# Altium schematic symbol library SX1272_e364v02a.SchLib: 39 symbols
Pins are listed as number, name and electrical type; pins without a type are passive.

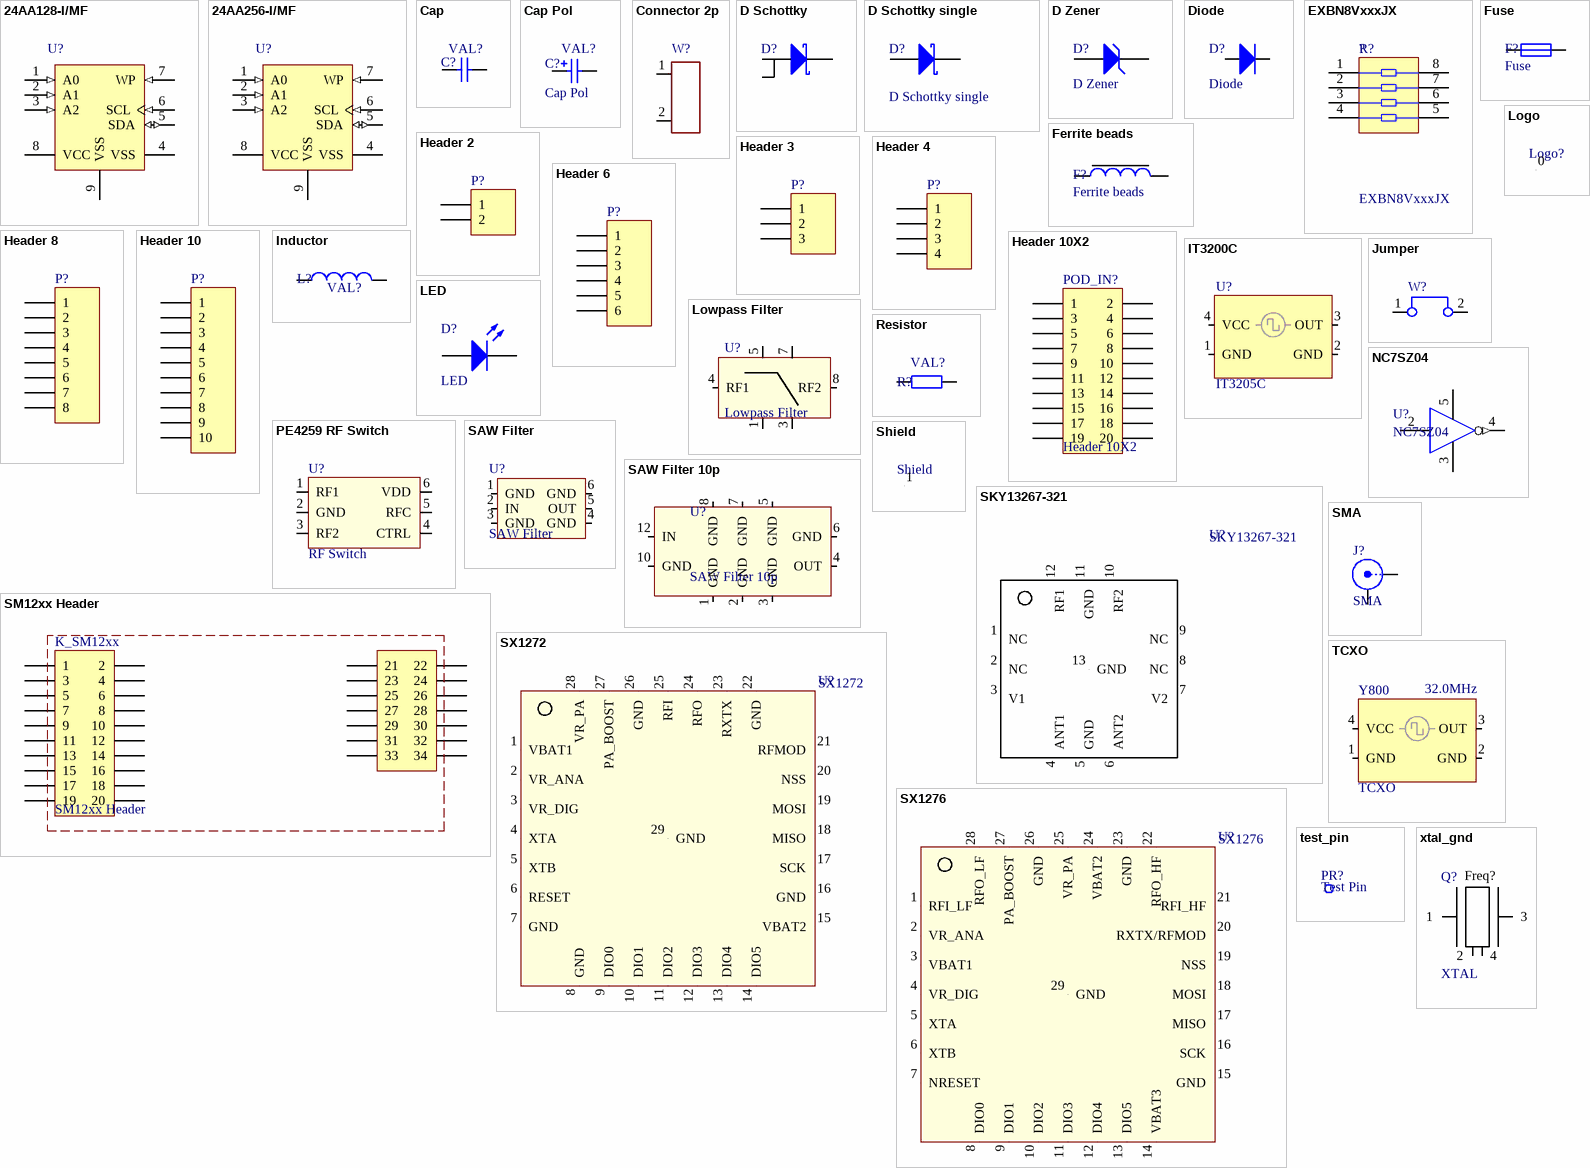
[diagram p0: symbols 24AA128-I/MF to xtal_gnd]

## 24AA128-I/MF
designator U?
128kbit, 400kHz, 1.7V, 8-Pin DFN, Industrial Temperature
footprint DFN8_ 5x6mm (8 Leads, Body 5x6mm, pitch 1.27mm, DFN8)
pins: 1 A0 (in), 2 A1 (in), 3 A2 (in), 4 VSS (power), 5 SDA (io), 6 SCL (in), 7 WP (in), 8 VCC (power), 9 VSS (power)

## 24AA256-I/MF
designator U?
256kbit, 400kHz, 1.7V, 8-Pin DFN, Industrial Temperature
footprint DFN8_ 5x6mm (8 Leads, Body 5x6mm, pitch 1.27mm, DFN8)
pins: 1 A0 (in), 2 A1 (in), 3 A2 (in), 4 VSS (power), 5 SDA (io), 6 SCL (in), 7 WP (in), 8 VCC (power), 9 VSS (power)

## Cap
designator C?  value VAL?  (hidden comment: Cap)
Capacitor SMD
simulation model CAP (Semiconductor Capacitor)
signal-integrity model Cap Semi
footprint rlc_402_smd (Chip SMD component 402; Body 1.0 x 0.5 mm (LxW typ))
footprint rlc_603_smd (Chip SMD component 603; Body 1.6 x 0.8mm (LxW typ))
footprint rlc_805_smd (Chip SMD component 805; Body 2.0 x 1.25 mm (LxW typ))
footprint rlc_1206_smd (Chip SMD component 1206; Body 3.2 x 1.6 mm (LxW typ))
footprint rlc_201_smd (Chip SMD component 201; Body 0.6 x 0.3 mm (LxW typ))
pins: 1, 2

## Cap Pol
designator C?  value VAL?
Polarized Capacitor (Surface Mount)
simulation model CAP (Capacitor)
signal-integrity model Cap Pol
footprint rlc_1210_smd (Chip SMD component 1210; Body 3.2 x 2.5 mm (LxW typ))
footprint rlc_1812_smd (Chip SMD component 1812; Body 4.5 x 3.2 mm (LxW typ))
footprint rlc_2225_smd (Chip SMD component 2225; Body 5.6 x 6.4 mm (LxW typ))
footprint CD3216-1206 (Chip Diode; Body 3.2 x 1.6 mm (LxW typ))
footprint CD2012-0805 (Chip Diode; Body 2.0 x 1.3 mm (LxW typ))
footprint rlc_1206_smd capa pol (Chip SMD component 1206; Body 3.2 x 1.6 mm (LxW typ))
pins: 1, 2
1 alternate drawing of the same symbol

## Connector 2p
designator W?  (value not drawn)
2pins Connector
footprint Connector 2p 2_54mm (Generic connector 2.54mm, 2 Leads 1mm;)
pins: 1, 2

## D Schottky
designator D?
Schottky Diode
footprint DPAK-369C-01 (DPAK-369C-01, 3-Leads, Body 6x6.22mm, Pitch 2.3mm, IPC Medium Density)
pins: 1 A, 3 A, 4 K

## D Schottky single
designator D?
Schottky Diode
footprint SOD123 (SOD123; Chip Diode; Body  2.7 x 1.6 mm (LxW typ))
pins: 1 A, 2 K

## D Zener
designator D?
Zener Diode
footprint CD1608-0603 (Chip Diode; Body 1.6 x 0.8 mm (LxW typ))
footprint CD2012-0805 (Chip Diode; Body 2.0 x 1.3 mm (LxW typ))
pins: 1 A, 2 K

## Diode
designator D?
Protection Diode
footprint CD1005-0402 (Chip Diode; Body 1.0 x 0.5 mm (LxW typ))
footprint CD1608-0603 (Chip Diode; Body 1.6 x 0.8 mm (LxW typ))
footprint CD2012-0805 (Chip Diode; Body 2.0 x 1.3 mm (LxW typ))
footprint CD3216-1206 (Chip Diode; Body 3.2 x 1.6 mm (LxW typ))
footprint PowerDI 123 (Chip Diode; PowerDI 123)
footprint DO214-AA (Chip Diode; Body 4.3 x3.6mm (LxW typ))
pins: 1 A, 2 K

## EXBN8VxxxJX
designator R?
Mini-Flat Package, Isolated Resistor Network, 0.031 W/resistor
footprint EXB28V (Chip Resistor Array, (0402x4); SM; 8 Leads; Body 2.10 x 1.10 mm (LxW max))
pins: 1, 2, 3, 4, 5, 6, 7, 8

## Ferrite beads
designator F?
Value: VAL?
footprint rlc_1206_smd (Chip SMD component 1206; Body 3.2 x 1.6 mm (LxW typ))
footprint rlc_805_smd (Chip SMD component 805; Body 2.0 x 1.25 mm (LxW typ))
footprint rlc_603_smd (Chip SMD component 603; Body 1.6 x 0.8mm (LxW typ))
footprint rlc_402_smd (Chip SMD component 402; Body 1.0 x 0.5 mm (LxW typ))
pins: 1, 2

## Fuse
designator F?
simulation model FUSE (Spice Subcircuit)
footprint rlc_1206_smd (Chip SMD component 1206; Body 3.2 x 1.6 mm (LxW typ))
footprint rlc_805_smd (Chip SMD component 805; Body 2.0 x 1.25 mm (LxW typ))
footprint rlc_603_smd (Chip SMD component 603; Body 1.6 x 0.8mm (LxW typ))
footprint rlc_402_smd (Chip SMD component 402; Body 1.0 x 0.5 mm (LxW typ))
pins: 1, 2

## Header 2
designator P?
Header, 2-Pin
footprint HDR1X2 (Connector; Header; 2 Position)
signal-integrity model Connector
pins: 1, 2

## Header 3
designator P?
Header, 3-Pin
footprint HDR1X3 (Connector; Header; 3 Position)
signal-integrity model Connector
pins: 1, 2, 3

## Header 4
designator P?
Header, 4-Pin
footprint HDR1X4 (Connector; Header; 4 Position)
signal-integrity model Connector
footprint 1125S-4P_connector (Connector; Header; 4 Position; P/N: 1125S-4P; Manuf: TAIFENG)
pins: 1, 2, 3, 4

## Header 6
designator P?
Header, 6-Pin
footprint HDR1X6 (Connector; Header; 6 Position)
signal-integrity model Connector
pins: 1, 2, 3, 4, 5, 6

## Header 8
designator P?
Header, 8-Pin
footprint HDR1X8 (Connector; Header; 8 Position)
signal-integrity model Connector
pins: 1, 2, 3, 4, 5, 6, 7, 8

## Header 10
designator P?
Header, 10-Pin
footprint HDR1X10 (Connector; Header; 10 Position)
signal-integrity model Connector
pins: 1, 2, 3, 4, 5, 6, 7, 8, 9, 10

## Header 10X2
designator POD_IN?
Header, 10-Pin, Dual row
footprint HDR2X10 (Connector; Header; 10x2 Position)
footprint HDR2X10 modif (Connector; Header; 10x2 Position - modified)
footprint SSW-110-01-F-D (Connector SMD; Header; 10x2 Position; Samtec)
pins: 1, 2, 3, 4, 5, 6, 7, 8, 9, 10, 11, 12, 13, 14, 15, 16, 17, 18, 19, 20

## Inductor
designator L?  value VAL?  (hidden comment: Inductor)
Code_IEC: 1005
footprint rlc_402_smd (Chip SMD component 402; Body 1.0 x 0.5 mm (LxW typ))
footprint rlc_1812_smd (Chip SMD component 1812; Body 4.5 x 3.2 mm (LxW typ))
footprint WE-PD2 Wurth 5.2 x 5.8mm (Chip Diode; Body  5.2 x 5.8mm (LxW typ))
footprint XFL4020 Series (Chip SMD component ; Body 4.0 x 4.0 mm (LxW typ))
pins: 1, 2

## IT3200C
designator U?, comment IT3205C
TCXO IT3205C - Rakon
footprint IT3200C TCXO (SMD 3.2x2.5mm for IT3200C TCXO)
pins: 1 GND, 2 GND, 3 OUT, 4 VCC

## Jumper
designator W?  (value not drawn)
Jumper Wire
footprint bridge_254mm (Generic Bridge 2.54mm, 2 Leads 1mm;)
footprint bridge_508mm (Generic Bridge 5.08mm, 2 Leads 1mm;)
pins: 1, 2

## LED
designator D?
footprint CD1005-0402 (Chip Diode; Body 1.0 x 0.5 mm (LxW typ))
footprint CD1608-0603 (Chip Diode; Body 1.6 x 0.8 mm (LxW typ))
footprint CD2012-0805 (Chip Diode; Body 2.0 x 1.3 mm (LxW typ))
footprint Reverse LED 3216 - 1206-hole round (Reverse Package Chip LED; Body 3.2 x 1.6 mm (LxW typ))
footprint Reverse LED 3216 - 1206 - hole slot (Reverse Package Chip LED; Body 3.2 x 1.6 mm (LxW typ))
pins: 1 A, 2 K

## Logo
designator Logo?, comment Logo symbol  (value not drawn)
Schematic symbol for Logo
footprint logo_semtech_horiz_size1 (Logo semtech horizontal - size1 - S)
footprint logo_semtech_horiz_size2 (Logo semtech horizontal - size2 - M)
footprint logo_semtech_horiz_size3 (Logo semtech horizontal - size3 - L)
footprint logo_semtech_horiz_size4 (Logo semtech horizontal - size4 - XL)
footprint Logo DC Supply (Logo for DC Supply)
footprint Logo LoRa Size1
footprint Logo LoRa Size2
footprint Logo LoRa Size3
footprint Logo LoRa Size4 (Logo LoRa Size4 - Top Overlay)
pins: 0 "Logo"

## Lowpass Filter
designator U?
RF Filter - Lowpass
footprint LP Filter Johanson (Low Pass Filter ; Body 2.00 x 1.25 mm (LxW max))
pins: 1 GND, 3 GND, 4 RF1, 5 GND, 7 GND, 8 RF2

## NC7SZ04
designator U?
NC7SZ04 - TinyLogic HS Single Inverter - Fairchild Semi
footprint SOT23-5 (SOT23, 5-Leads, Body 2.9x1.6mm, Pitch 0.95mm, Lead Span 2.8mm, IPC Medium Density)
footprint SC70-5 (SC70 5-Leads, Body 2.0x1.25mm, Pitch 0.65mm)
pins: 2 A, 3 GND (power), 4 Y (out), 5 VCC (power)

## PE4259 RF Switch
designator U?, comment RF Switch
PE4259 Peregrine RF Switch
footprint SC70-6 (SC70 6-Leads, Body 2.0x1.25mm, Pitch 0.65mm)
pins: 1 RF1, 2 GND, 3 RF2, 4 CTRL, 5 RFC, 6 VDD

## Resistor
designator R?  value VAL?  (hidden comment: Resistor)
Resistor SMD - IEC symbol version
footprint rlc_201_smd (Chip SMD component 201; Body 0.6 x 0.3 mm (LxW typ))
footprint rlc_402_smd (Chip SMD component 402; Body 1.0 x 0.5 mm (LxW typ))
footprint rlc_603_smd (Chip SMD component 603; Body 1.6 x 0.8mm (LxW typ))
footprint rlc_805_smd (Chip SMD component 805; Body 2.0 x 1.25 mm (LxW typ))
footprint rlc_1206_smd (Chip SMD component 1206; Body 3.2 x 1.6 mm (LxW typ))
pins: 1, 2

## SAW Filter
designator U?
SAW Filter - Bandpass - TEMEX type
footprint sc44_3.8x3.8mm (sc44 footprint, 3.8x3.8mm)
footprint DCC6C_3.0x3.0mm (DCC6C footprint, 3.0x3.0mm)
pins: 1 GND, 2 IN, 3 GND, 4 GND, 5 OUT, 6 GND

## SAW Filter 10p
designator U?
SAW Filter 10p  - Bandpass - RFM type
footprint 7.0x5.0mm SMD package (7.0x5.0mm SMD package - 10pins)
pins: 1 GND, 2 GND, 3 GND, 4 OUT, 5 GND, 6 GND, 7 GND, 8 GND, 10 GND, 12 IN

## Shield
designator Shield, comment Logo symbol  (value not drawn)
Shield - EMI Gasket - Standard Surface Mount Shields
footprint BMIS-205-F - Shield (BMIS-205-F EMI Gasket - Standard Surface Mount Shields -  Laird Technologies)
pins: 1 "Shield"

## SKY13267-321
designator U?
SKY13267-321 - T/R Diversity Switch LF-6GHz - Modified labelling
footprint vqfn12_3x3mm (12 Leads, Body 3.0x3.0mm, Pitch 0.50mm, VQFN12)
pins: 1 NC, 2 NC, 3 V1, 4 ANT1, 5 GND, 6 ANT2, 7 V2, 8 NC, 9 NC, 10 RF2, 11 GND, 12 RF1, 13 GND

## SM12xx Header
designator K_SM12xx
SM12xx Header; 34pins: 2x10pins + 2x7pins
footprint HDR34 Header (Connector; Header; 34 Position - SM12xx Header)
pins: 1, 2, 3, 4, 5, 6, 7, 8, 9, 10, 11, 12, 13, 14, 15, 16, 17, 18, 19, 20, 21, 22, 23, 24, 25, 26, 27, 28, 29, 30, 31, 32, 33, 34

## SMA
designator J?
SMA Straight Connector
footprint SMA Straight SMD (SMA Connector; Straight; SMD)
footprint SMA END LAUNCH JACK RECEPTACLE (SMA Connector - End Launch Jack Receptacle)
footprint SMA Straight (SMA Connector; Straight)
footprint SMA END LAUNCH JACK RECEPTACLE SHORT (SMA Connector - End Launch Jack Receptacle - Short)
pins: 1 Signal "RF signal", 2 GND "Ground signal"

## SX1272
designator U?
SX1272 - Low Power Integrated UHF Transceiver with Lora technology
footprint vqfn28_6x6mm (28 Leads, Body 6.0x6.0mm, Pitch 0.65mm, VQFN28)
pins: 1 VBAT1, 2 VR_ANA, 3 VR_DIG, 4 XTA, 5 XTB, 6 RESET, 7 GND, 8 GND, 9 DIO0, 10 DIO1, 11 DIO2, 12 DIO3, 13 DIO4, 14 DIO5, 15 VBAT2, 16 GND, 17 SCK, 18 MISO, 19 MOSI, 20 NSS, 21 RFMOD, 22 GND, 23 RXTX, 24 RFO, 25 RFI, 26 GND, 27 PA_BOOST, 28 VR_PA, 29 GND

## SX1276
designator U?
SX1276 - Low Power Integrated UHF Transceiver with loRa Modem
footprint vqfn28_6x6mm (28 Leads, Body 6.0x6.0mm, Pitch 0.65mm, VQFN28)
pins: 1 RFI_LF, 2 VR_ANA, 3 VBAT1, 4 VR_DIG, 5 XTA, 6 XTB, 7 NRESET, 8 DIO0, 9 DIO1, 10 DIO2, 11 DIO3, 12 DIO4, 13 DIO5, 14 VBAT3, 15 GND, 16 SCK, 17 MISO, 18 MOSI, 19 NSS, 20 RXTX/RFMOD, 21 RFI_HF, 22 RFO_HF, 23 GND, 24 VBAT2, 25 VR_PA, 26 GND, 27 PA_BOOST, 28 RFO_LF, 29 GND

## TCXO
designator Y800  value 32.0MHz
footprint IT3200C TCXO (SMD 3.2x2.5mm for IT3200C TCXO)
footprint TCXO 3.2x2.5mm (SMD 3.2x2.5mm for TCXO or VCTCXO)
footprint TCXO 3.2x2.5mm_2.0x1.6mm (SMD 3.2x2.5mm & 2.0x1.6mm compatible for TCXO or VCTCXO)
footprint TCXO 2.0x1.6mm (SMD 2.0x1.6mm for TCXO or VCTCXO)
pins: 1 GND, 2 GND, 3 OUT, 4 VCC

## test_pin
designator PR?, comment Test Pin
footprint pin_1mm (Generic Pin 1.1mm; 1 Lead)
footprint pin_1.1mm (Generic Pin 1.1mm; 1 Lead)
footprint pin_SMD (Generic Pin; 1 pin SMD)
pins: 1 pin  "Test Pin"

## xtal_gnd
designator Q?, comment XTAL  value Freq?
Crystal with GND pins
footprint nd2520da (Crystal SMD 2.5x2.0mm)
footprint nd3225da - nd2520da (Crystal SMD 3.2x2.5mm compatible with 2.5x2.0mm)
footprint nd2016da (Crystal SMD 2.0x1.6mm)
footprint nd3225da (Crystal SMD 3.2x2.5mm)
pins: 1, 2, 3, 4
